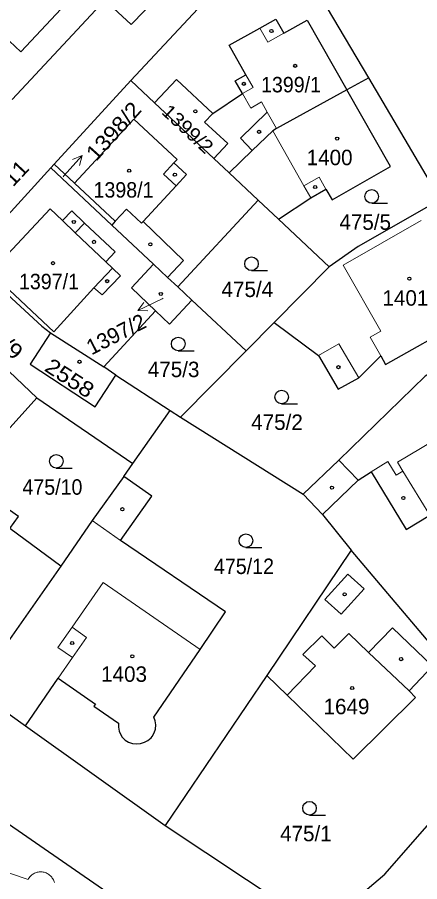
# Model space of a CAD drawing. Extents: x -679733 to -673243, y -1075091 to -1066557.
# Drawn here: x -675685.5 to -675641.2, y -1072340.3 to -1072245.1 of the extents above; entities that cross this region are included whole.
import ezdxf
from ezdxf.enums import TextEntityAlignment as Align

# ---------------------------------------------------------------- set-up
doc = ezdxf.new("R2010")
doc.units = 0
doc.header["$LTSCALE"] = 0.68
for name, color, linetype, lineweight in [('1', 7, 'Continuous', 25), ('3', 7, 'Continuous', 25), ('4', 7, 'Continuous', 13), ('5', 7, 'Continuous', 25), ('7', 7, 'Continuous', 13)]:
    doc.layers.add(name, color=color, linetype=linetype, lineweight=lineweight)
doc.layers.add('2', color=7, linetype='Continuous')

msp = doc.modelspace()

# ---------------------------------------------------------------- linework, layer by layer
at = {"layer": '1'}
for p, q in [((-675646.8, -1072251.8), (-675655.8, -1072236.62)), ((-675686.1, -1072254.17), (-675675.87, -1072243.22)), ((-675681.45, -1072261.29), (-675681.83, -1072261.71)), ((-675659.01, -1072265.24), (-675656.74, -1072267.36)), ((-675651.17, -1072272.59), (-675656.74, -1072267.36)), ((-675674.69, -1072284.54), (-675675.99, -1072283.61)), ((-675673.81, -1072295.67), (-675672.8, -1072294.25)), ((-675651.92, -1072299.85), (-675648.74, -1072303.81)), ((-675658.05, -1072317.58), (-675669.24, -1072334.12)), ((-675684.63, -1072323.15), (-675669.24, -1072334.12))]:
    msp.add_line(p, q, dxfattribs=at)
for points in [[(-675675.87, -1072243.22), (-675673, -1072245.92), (-675658.41, -1072230.92), (-675651.43, -1072224.24)], [(-675655.8, -1072236.62), (-675658.25, -1072236.27), (-675673.03, -1072252.09)], [(-675675.24, -1072344.8), (-675677.06, -1072343.56), (-675675.65, -1072341.45), (-675809.62, -1072248.86), (-675810.47, -1072252.39), (-675814.41, -1072249.48), (-675828.02, -1072240.66), (-675831.19, -1072238.38), (-675834.37, -1072240.28), (-675799.8, -1072264.22)], [(-675663.99, -1072255.71), (-675660.73, -1072253.52), (-675661.52, -1072252.12), (-675660.34, -1072251.45), (-675662.19, -1072248.19), (-675658.8, -1072246.3), (-675657.06, -1072245.32), (-675656.18, -1072246.88), (-675653.59, -1072245.44), (-675649.22, -1072253.12)], [(-675663.89, -1072260.67), (-675670.41, -1072254.55), (-675673.03, -1072252.09), (-675681.45, -1072261.29)], [(-675670.41, -1072254.55), (-675667.99, -1072251.98), (-675663.99, -1072255.71)], [(-675638.91, -1072265.18), (-675646.8, -1072251.8), (-675649.22, -1072253.12)], [(-675649.22, -1072253.12), (-675656.97, -1072257.36), (-675657.4, -1072257.61), (-675659.64, -1072259.78), (-675662.19, -1072262.26)], [(-675656.74, -1072267.36), (-675653.19, -1072265), (-675651.53, -1072264.06), (-675650.86, -1072265.23), (-675644.41, -1072261.56), (-675649.22, -1072253.12)], [(-675663.99, -1072255.71), (-675664.89, -1072256.67), (-675662.35, -1072259.03), (-675663.89, -1072260.67)], [(-675667.86, -1072274.8), (-675659.01, -1072265.24), (-675662.19, -1072262.26), (-675663.89, -1072260.67)], [(-675670.3, -1072277.43), (-675672.96, -1072274.92), (-675670.52, -1072272.31), (-675675.12, -1072267.99), (-675681.83, -1072261.71), (-675690.93, -1072271.66)], [(-675681.45, -1072261.29), (-675679.24, -1072263.39), (-675674.73, -1072267.57), (-675675.12, -1072267.99)], [(-675638.91, -1072265.18), (-675647.97, -1072270.34), (-675651.17, -1072272.59), (-675657.25, -1072278.74)], [(-675657.25, -1072278.74), (-675652.36, -1072282.36), (-675650.18, -1072286.06), (-675647.91, -1072284.83), (-675645.5, -1072282.4), (-675644.96, -1072283.36), (-675636.49, -1072278.56), (-675635.21, -1072277.83), (-675632.4, -1072276.24), (-675638.91, -1072265.18)], [(-675690.93, -1072271.66), (-675682.82, -1072279.13), (-675681.87, -1072279.86)], [(-675667.86, -1072274.8), (-675668.97, -1072273.76), (-675670.52, -1072272.31)], [(-675670.3, -1072277.43), (-675668.76, -1072278.89), (-675666.31, -1072276.26), (-675667.86, -1072274.8)], [(-675683.37, -1072287.03), (-675687.2, -1072283.39), (-675689.4, -1072281.4), (-675691.65, -1072279.37), (-675695.05, -1072276.14)], [(-675657.25, -1072278.74), (-675660.33, -1072281.85), (-675666.31, -1072276.26)], [(-675681.87, -1072279.86), (-675675.99, -1072283.61), (-675670.3, -1072277.43)], [(-675630.88, -1072278.84), (-675640.61, -1072284.65), (-675650.13, -1072293.87), (-675654.03, -1072297.62), (-675651.92, -1072299.85)], [(-675681.87, -1072279.86), (-675684.11, -1072283.3), (-675676.94, -1072288.01), (-675674.69, -1072284.54)], [(-675660.33, -1072281.85), (-675667.54, -1072289.14), (-675654.03, -1072297.62)], [(-675674.69, -1072284.54), (-675668.69, -1072288.42), (-675667.54, -1072289.14)], [(-675651.92, -1072299.85), (-675648, -1072296.07), (-675646.55, -1072295.16), (-675642.71, -1072301.51), (-675640.09, -1072299.95), (-675637.2, -1072304.82), (-675630.71, -1072300.99), (-675629.71, -1072302.68), (-675626.28, -1072300.62), (-675627.27, -1072298.95), (-675625.97, -1072298.18), (-675628.73, -1072293.57), (-675628.28, -1072293.3), (-675631.98, -1072287.09), (-675627.53, -1072284.42)], [(-675690.86, -1072295.31), (-675689.27, -1072293.55), (-675683.37, -1072287.03)], [(-675683.37, -1072287.03), (-675672.8, -1072294.25), (-675668.69, -1072288.42)], [(-675680.72, -1072305.54), (-675686.36, -1072301.42), (-675685.4, -1072300.1), (-675689.41, -1072297.31), (-675690.86, -1072295.31)], [(-675673.81, -1072295.67), (-675677.27, -1072300.54), (-675680.72, -1072305.54), (-675686.66, -1072313.99), (-675690.25, -1072319.15), (-675684.63, -1072323.15)], [(-675670.5, -1072322.19), (-675665.37, -1072314.74), (-675662.61, -1072310.58), (-675674.15, -1072302.73), (-675670.71, -1072297.84), (-675673.81, -1072295.67)], [(-675638.83, -1072315.52), (-675648.74, -1072303.81), (-675658.05, -1072317.58)], [(-675658.05, -1072317.58), (-675655.81, -1072319.75), (-675648.53, -1072326.82), (-675641.67, -1072320.01), (-675642.38, -1072319.3), (-675639.79, -1072316.55), (-675638.83, -1072315.52)], [(-675684.63, -1072323.15), (-675681.02, -1072317.88), (-675676.92, -1072320.74), (-675677.08, -1072320.97), (-675674.38, -1072322.85)], [(-675674.38, -1072322.85), (-675674.396, -1072323.295), (-675674.313, -1072323.732), (-675674.134, -1072324.139), (-675673.961, -1072324.39), (-675673.644, -1072324.702), (-675673.266, -1072324.936), (-675672.844, -1072325.079), (-675672.402, -1072325.125), (-675671.96, -1072325.07), (-675671.53, -1072324.954), (-675671.137, -1072324.746), (-675670.8, -1072324.455), (-675670.669, -1072324.298), (-675670.444, -1072323.914), (-675670.31, -1072323.49), (-675670.275, -1072323.046), (-675670.339, -1072322.605), (-675670.5, -1072322.19)], [(-675669.24, -1072334.12), (-675655.8, -1072343.03), (-675653.77, -1072343.98), (-675652.23, -1072344.22), (-675650.78, -1072343.84), (-675649.38, -1072343.04), (-675648.22, -1072342.16), (-675645.05, -1072339.48), (-675631.58, -1072324.1), (-675631.9, -1072323.72)]]:
    msp.add_lwpolyline(points, dxfattribs=at)
at = {"layer": '3'}
for p, q in [((-675646.493, -1072265.59), (-675644.743, -1072265.59)), ((-675659.733, -1072273.01), (-675657.983, -1072273.01)), ((-675667.803, -1072281.84), (-675666.053, -1072281.84)), ((-675656.413, -1072287.68), (-675654.663, -1072287.68)), ((-675681.233, -1072294.76), (-675679.483, -1072294.76)), ((-675660.353, -1072303.5), (-675658.603, -1072303.5)), ((-675653.343, -1072332.96), (-675651.593, -1072332.96))]:
    msp.add_line(p, q, dxfattribs=at)
for centre in [(-675646.4929, -1072264.8398), (-675659.7329, -1072272.2598), (-675667.8029, -1072281.0898), (-675656.4129, -1072286.9298), (-675681.2329, -1072294.0098), (-675660.3529, -1072302.7498), (-675653.3429, -1072332.2098)]:
    msp.add_circle(centre, 0.75, dxfattribs=at)
at = {"layer": '4'}
for p, q in [((-675685.13, -1072248.92), (-675678.32, -1072241.61)), ((-675688.36, -1072245.9), (-675685.13, -1072248.92)), ((-675658.8, -1072246.3), (-675657.93, -1072247.85)), ((-675657.93, -1072247.85), (-675656.18, -1072246.88)), ((-675659.55, -1072252.84), (-675660.34, -1072251.45)), ((-675660.73, -1072253.52), (-675659.55, -1072252.84)), ((-675659.82, -1072255.11), (-675660.73, -1072253.52)), ((-675658.64, -1072254.43), (-675659.82, -1072255.11)), ((-675658, -1072255.56), (-675658.64, -1072254.43)), ((-675660.95, -1072258.43), (-675658, -1072255.56)), ((-675656.97, -1072257.36), (-675658, -1072255.56)), ((-675679.24, -1072263.39), (-675672.68, -1072256.33)), ((-675672.68, -1072256.33), (-675667.93, -1072260.76)), ((-675657.4, -1072257.61), (-675653.95, -1072263.66)), ((-675659.64, -1072259.78), (-675660.95, -1072258.43)), ((-675667.93, -1072260.76), (-675668.27, -1072261.13)), ((-675668.27, -1072261.13), (-675669.43, -1072262.38)), ((-675668.27, -1072261.13), (-675666.88, -1072262.42)), ((-675669.43, -1072262.38), (-675668.03, -1072263.69)), ((-675666.88, -1072262.42), (-675668.03, -1072263.69)), ((-675653.95, -1072263.66), (-675652.29, -1072262.72)), ((-675652.29, -1072262.72), (-675651.53, -1072264.06)), ((-675653.95, -1072263.66), (-675653.19, -1072265)), ((-675688.47, -1072273.23), (-675681.91, -1072266.21)), ((-675680.55, -1072267.51), (-675681.91, -1072266.21)), ((-675680.55, -1072267.51), (-675679.53, -1072266.43)), ((-675679.53, -1072266.43), (-675678.12, -1072267.78)), ((-675674.73, -1072267.57), (-675673.5, -1072266.26)), ((-675673.5, -1072266.26), (-675671.86, -1072267.78)), ((-675679.14, -1072268.85), (-675680.55, -1072267.51)), ((-675641.05, -1072267.5), (-675649.62, -1072272.4)), ((-675678.12, -1072267.78), (-675679.14, -1072268.85)), ((-675678.12, -1072267.78), (-675674.76, -1072270.93)), ((-675671.86, -1072267.78), (-675671.68, -1072267.59)), ((-675675.79, -1072272.03), (-675679.14, -1072268.85)), ((-675674.76, -1072270.93), (-675675.79, -1072272.03)), ((-675675.03, -1072272.75), (-675675.79, -1072272.03)), ((-675668.97, -1072273.76), (-675667.22, -1072271.89)), ((-675688.47, -1072273.23), (-675681.52, -1072279.75)), ((-675677.09, -1072274.92), (-675675.03, -1072272.75)), ((-675675.03, -1072272.75), (-675674.16, -1072273.57)), ((-675649.62, -1072272.4), (-675645.48, -1072279.67)), ((-675674.16, -1072273.57), (-675676.18, -1072275.69)), ((-675681.52, -1072279.75), (-675677.09, -1072274.92)), ((-675676.18, -1072275.69), (-675677.09, -1072274.92)), ((-675645.48, -1072279.67), (-675646.67, -1072280.34)), ((-675645.5, -1072282.4), (-675646.67, -1072280.34)), ((-675652.36, -1072282.36), (-675650.11, -1072281.09)), ((-675650.11, -1072281.09), (-675647.91, -1072284.83)), ((-675643.67, -1072294.09), (-675639.77, -1072291.78)), ((-675650.13, -1072293.87), (-675648, -1072296.07)), ((-675646.55, -1072295.16), (-675644.71, -1072294.03)), ((-675644.71, -1072294.03), (-675643.79, -1072295.52)), ((-675643.07, -1072295.08), (-675643.67, -1072294.09)), ((-675643.79, -1072295.52), (-675643.07, -1072295.08)), ((-675640.09, -1072299.95), (-675643.07, -1072295.08)), ((-675677.27, -1072300.54), (-675674.15, -1072302.73)), ((-675651.67, -1072309.21), (-675649.13, -1072306.42)), ((-675649.13, -1072306.42), (-675647.33, -1072308.05)), ((-675679.49, -1072312.28), (-675676.07, -1072307.37)), ((-675676.07, -1072307.37), (-675665.37, -1072314.74)), ((-675647.33, -1072308.05), (-675649.87, -1072310.85)), ((-675649.87, -1072310.85), (-675651.67, -1072309.21)), ((-675681.05, -1072314.51), (-675679.49, -1072312.28)), ((-675679.49, -1072312.28), (-675677.9, -1072313.4)), ((-675654.06, -1072315.28), (-675651.98, -1072313.21)), ((-675651.98, -1072313.21), (-675650.62, -1072314.58)), ((-675650.62, -1072314.58), (-675649.01, -1072312.98)), ((-675649.01, -1072312.98), (-675646.85, -1072315.08)), ((-675646.85, -1072315.08), (-675644.21, -1072312.35)), ((-675644.21, -1072312.35), (-675639.79, -1072316.55)), ((-675677.9, -1072313.4), (-675679.45, -1072315.62)), ((-675679.45, -1072315.62), (-675681.05, -1072314.51)), ((-675646.85, -1072315.08), (-675642.38, -1072319.3)), ((-675681.02, -1072317.88), (-675679.45, -1072315.62)), ((-675652.67, -1072316.52), (-675654.06, -1072315.28)), ((-675655.81, -1072319.75), (-675652.67, -1072316.52)), ((-675686.4, -1072339.36), (-675684.34, -1072340.05))]:
    msp.add_line(p, q, dxfattribs=at)
for points in [[(-675668.03, -1072263.69), (-675671.68, -1072267.59), (-675667.22, -1072271.89)], [(-675684.34, -1072340.05), (-675684.285, -1072339.954), (-675684.223, -1072339.862), (-675684.155, -1072339.774), (-675684.081, -1072339.692), (-675684.001, -1072339.615), (-675683.916, -1072339.544), (-675683.826, -1072339.479), (-675683.732, -1072339.421), (-675683.634, -1072339.37), (-675683.532, -1072339.325), (-675683.428, -1072339.288), (-675683.321, -1072339.259), (-675683.212, -1072339.237), (-675683.102, -1072339.223), (-675682.991, -1072339.216), (-675682.881, -1072339.218), (-675682.77, -1072339.227), (-675682.661, -1072339.244), (-675682.553, -1072339.269), (-675682.447, -1072339.302), (-675682.343, -1072339.342), (-675682.243, -1072339.389), (-675682.146, -1072339.443), (-675682.054, -1072339.504), (-675681.966, -1072339.572), (-675681.883, -1072339.645), (-675681.805, -1072339.724), (-675681.733, -1072339.809), (-675681.668, -1072339.898), (-675681.609, -1072339.992), (-675681.556, -1072340.089), (-675681.511, -1072340.191), (-675681.473, -1072340.295), (-675681.442, -1072340.401)]]:
    msp.add_lwpolyline(points, dxfattribs=at)
at = {"layer": '5'}
for centre in [(-675657.5368, -1072246.6292), (-675654.9268, -1072250.4592), (-675660.5768, -1072252.4392), (-675665.9168, -1072255.4792), (-675658.8968, -1072257.7292), (-675650.2968, -1072258.4792), (-675673.2068, -1072262.0092), (-675668.1668, -1072262.4492), (-675652.7168, -1072263.8092), (-675679.2968, -1072267.6492), (-675677.0868, -1072269.8492), (-675670.8668, -1072270.1092), (-675681.5868, -1072272.1892), (-675675.6268, -1072274.1692), (-675642.3468, -1072273.8992), (-675669.7168, -1072275.5792), (-675678.6768, -1072283.0492), (-675650.1568, -1072283.6392), (-675650.8668, -1072296.9092), (-675643.0068, -1072298.0492), (-675673.9568, -1072299.2892), (-675649.4768, -1072308.6592), (-675679.4868, -1072314.0192), (-675672.8568, -1072315.4792), (-675643.2568, -1072315.7892), (-675648.6468, -1072318.9792)]:
    msp.add_circle(centre, 0.175, dxfattribs=at)
at = {"layer": '7'}
for p, q in [((-675678.392, -1072260.35), (-675679.434, -1072260.759)), ((-675672.267, -1072277.416), (-675671.148, -1072277.427))]:
    msp.add_line(p, q, dxfattribs=at)
for points in [[(-675680.48, -1072262.67), (-675680.4, -1072262.58), (-675678.392, -1072260.35), (-675678.69, -1072261.429)], [(-675669.47, -1072276.05), (-675669.57, -1072276.1), (-675672.267, -1072277.416), (-675671.587, -1072276.526)]]:
    msp.add_lwpolyline(points, dxfattribs=at)

# ---------------------------------------------------------------- texts
at = {"layer": '2', "width": 0.95}
for s, p in [('1399/1', (-675655.379, -1072253.38)), ('1398/1', (-675673.829, -1072264.97)), ('1397/1', (-675682.039, -1072275.06)), ('475/10', (-675681.659, -1072297.69)), ('475/12', (-675660.559, -1072306.42))]:
    msp.add_text(s, height=1.7, dxfattribs=at).set_placement(p, align=Align.CENTER)
at = {"layer": '2', "width": 1.1}
msp.add_text('1398/2', height=1.7, rotation=48, dxfattribs=at).set_placement((-675676.848, -1072261.058))
at = {"layer": '2'}
for s, height, rotation, width, p in [('1399/2', 1.5, 317, 1.1, (-675667.2695, -1072257.9565)), ('476/11', 1.7, 47, 1.1, (-675686.7174, -1072264.6332)), ('475/9', 1.7, 317, 1.15, (-675688.2732, -1072280.7318)), ('2558', 1.7, 327, 1.15, (-675680.2134, -1072285.5531))]:
    msp.add_text(s, height=height, rotation=rotation, dxfattribs=dict(at, width=width)).set_placement(p, align=Align.CENTER)
for s, p in [('1400', (-675651.13, -1072261.4)), ('475/5', (-675647.21, -1072268.519)), ('475/4', (-675660.19, -1072275.92)), ('1401', (-675642.78, -1072276.87)), ('475/3', (-675668.31, -1072284.739)), ('475/2', (-675656.92, -1072290.55)), ('1403', (-675673.77, -1072318.29)), ('1649', (-675649.27, -1072321.86)), ('475/1', (-675653.74, -1072335.85))]:
    msp.add_text(s, height=1.7, dxfattribs=at).set_placement(p, align=Align.CENTER)
msp.add_text('1397/2', height=1.7, rotation=27, dxfattribs=at).set_placement((-675671.1588, -1072279.1924), align=Align.RIGHT)

doc.saveas('drawing.dxf')
